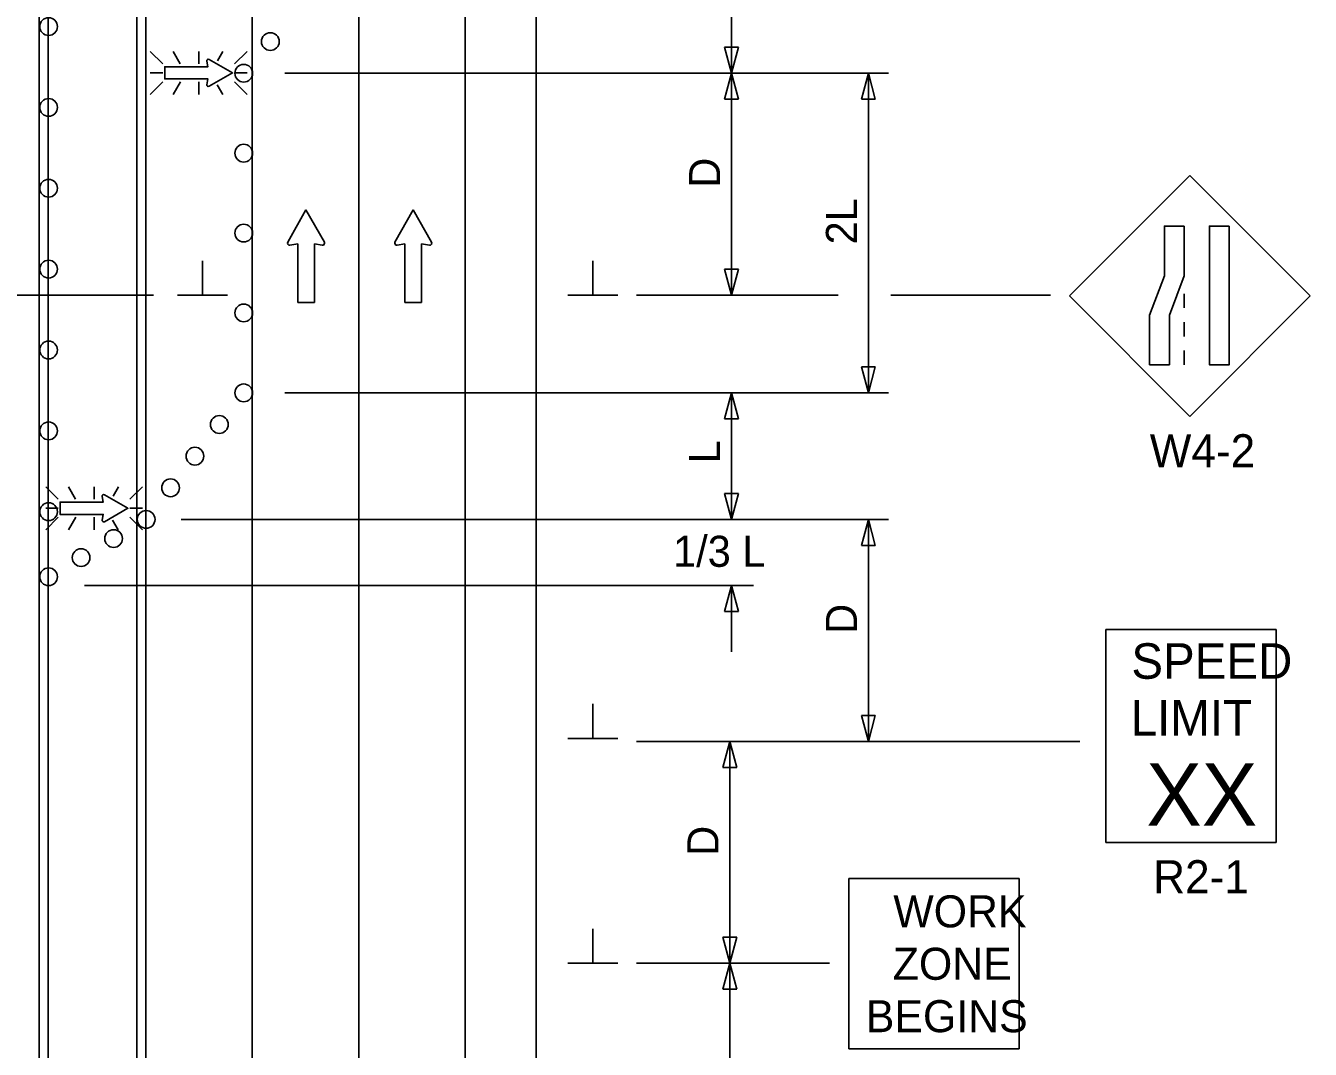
# Model space of a CAD drawing. Extents: x 16732 to 18475, y 5726 to 6929.
# Drawn here: x 17046.3 to 17335.8, y 6299.5 to 6530.1 of the extents above; entities that cross this region are included whole.
import ezdxf

# ---------------------------------------------------------------- set-up
doc = ezdxf.new("R2010")
doc.units = 0
for name, color, linetype in [('ALI_LEGAL_EX', 7, 'Continuous'), ('MT_SCRATCH_LEVEL_E', 7, 'Continuous'), ('PAVT_EDGE_EX', 7, 'Continuous'), ('TRAFFIC_SIGNS_PR', 7, 'Continuous'), ('TYPICAL_TEXT_DIMEN_PR', 7, 'Continuous')]:
    doc.layers.add(name, color=color, linetype=linetype)

msp = doc.modelspace()

# ---------------------------------------------------------------- linework, layer by layer
at = {"layer": 'ALI_LEGAL_EX'}
for p, q in [((17051.36, 6131.68), (17051.36, 6928.96)), ((17071.36, 6131.68), (17071.36, 6928.96)), ((17097.36, 6131.68), (17097.36, 6928.96)), ((17121.36, 6131.68), (17121.36, 6928.96))]:
    msp.add_line(p, q, dxfattribs=at)
for points in [[(17051.36, 6431.68), (17051.36, 6456.68)], [(17071.36, 6431.68), (17071.36, 6456.68)], [(17121.36, 6431.68), (17121.36, 6456.68)], [(17051.36, 6331.68), (17051.36, 6356.68)], [(17071.36, 6331.68), (17071.36, 6356.68)], [(17097.36, 6331.68), (17097.36, 6356.68)], [(17121.36, 6331.68), (17121.36, 6356.68)]]:
    msp.add_lwpolyline(points, dxfattribs=at)
at = {"layer": 'MT_SCRATCH_LEVEL_E'}
for p, q in [((17109.46, 6488.6), (17105.35, 6481.36)), ((17109.46, 6488.6), (17105.35, 6481.36)), ((17113.61, 6481.36), (17109.46, 6488.6)), ((17113.61, 6481.36), (17109.46, 6488.6)), ((17133.63, 6488.6), (17129.52, 6481.36)), ((17133.63, 6488.6), (17129.52, 6481.36)), ((17137.78, 6481.36), (17133.63, 6488.6)), ((17137.78, 6481.36), (17133.63, 6488.6)), ((17105.83, 6480.67), (17107.61, 6480.99)), ((17105.83, 6480.67), (17107.61, 6480.99)), ((17107.61, 6480.99), (17107.61, 6467.73)), ((17107.61, 6480.99), (17107.61, 6467.73)), ((17111.35, 6467.73), (17111.35, 6480.99)), ((17111.35, 6480.99), (17113.13, 6480.67)), ((17111.35, 6467.73), (17111.35, 6480.99)), ((17111.35, 6480.99), (17113.13, 6480.67)), ((17130, 6480.67), (17131.78, 6480.99)), ((17130, 6480.67), (17131.78, 6480.99)), ((17131.78, 6480.99), (17131.78, 6467.73)), ((17131.78, 6480.99), (17131.78, 6467.73)), ((17135.52, 6467.73), (17135.52, 6480.99)), ((17135.52, 6480.99), (17137.3, 6480.67)), ((17135.52, 6467.73), (17135.52, 6480.99)), ((17135.52, 6480.99), (17137.3, 6480.67)), ((17107.61, 6467.73), (17111.35, 6467.73)), ((17107.61, 6467.73), (17111.35, 6467.73)), ((17131.78, 6467.73), (17135.52, 6467.73)), ((17131.78, 6467.73), (17135.52, 6467.73))]:
    msp.add_line(p, q, dxfattribs=at)
for centre, start, end in [((17105.76, 6481.13), 150.4248, 279.9638), ((17105.76, 6481.13), 150.4248, 279.9638), ((17113.2, 6481.13), 260.0362, 29.7731), ((17113.2, 6481.13), 260.0362, 29.7731), ((17129.93, 6481.13), 150.4248, 279.9638), ((17129.93, 6481.13), 150.4248, 279.9638), ((17137.37, 6481.13), 260.0362, 29.7731), ((17137.37, 6481.13), 260.0362, 29.7731)]:
    msp.add_arc(centre, 0.463, start, end, dxfattribs=at)
at = {"layer": 'PAVT_EDGE_EX'}
for p, q in [((17049.36, 6924.76), (17049.36, 6059.7)), ((17073.36, 6924.76), (17073.36, 6059.7)), ((17145.36, 6924.76), (17145.36, 6059.7)), ((17161.36, 6924.76), (17161.36, 6059.7))]:
    msp.add_line(p, q, dxfattribs=at)
at = {"layer": 'TRAFFIC_SIGNS_PR'}
for p, q in [((17077.21, 6521.51), (17074.38, 6524.33)), ((17079.5, 6524.32), (17081.13, 6521.51)), ((17085.29, 6521.51), (17085.29, 6524.32)), ((17090.76, 6524.32), (17089.55, 6522.23)), ((17096.19, 6524.32), (17093.38, 6521.51)), ((17077.21, 6519.47), (17074.38, 6519.47)), ((17077.21, 6517.44), (17074.38, 6514.62)), ((17081.15, 6517.44), (17079.53, 6514.62)), ((17085.29, 6517.44), (17085.29, 6514.62)), ((17093.38, 6519.47), (17096.19, 6519.47)), ((17096.19, 6514.62), (17093.38, 6517.44)), ((17089.47, 6516.81), (17090.73, 6514.62)), ((17308.67, 6496.38), (17281.52, 6469.23)), ((17335.82, 6469.23), (17308.67, 6496.38)), ((17281.52, 6469.23), (17308.67, 6442.08)), ((17307.42, 6469.72), (17307.42, 6466.52)), ((17308.67, 6442.08), (17335.82, 6469.23)), ((17307.42, 6463.32), (17307.42, 6460.12)), ((17307.42, 6456.92), (17307.42, 6453.72)), ((17053.62, 6423.42), (17050.8, 6426.24)), ((17055.92, 6426.24), (17057.55, 6423.42)), ((17061.71, 6423.42), (17061.71, 6426.24)), ((17067.18, 6426.24), (17065.97, 6424.15)), ((17072.61, 6426.24), (17069.79, 6423.42)), ((17053.62, 6421.39), (17050.8, 6421.39)), ((17053.62, 6419.36), (17050.8, 6416.54)), ((17057.57, 6419.36), (17055.95, 6416.54)), ((17061.71, 6419.36), (17061.71, 6416.54)), ((17069.79, 6421.39), (17072.61, 6421.39)), ((17072.61, 6416.54), (17069.79, 6419.36)), ((17065.89, 6418.72), (17067.15, 6416.54)), ((17289.74, 6394.12), (17328.14, 6394.12)), ((17289.74, 6346.12), (17289.74, 6394.12)), ((17328.14, 6346.12), (17328.14, 6394.12)), ((17289.74, 6346.12), (17328.14, 6346.12)), ((17231.84, 6299.62), (17231.84, 6338.02)), ((17231.84, 6338.02), (17270.24, 6338.02)), ((17270.24, 6299.62), (17270.24, 6338.02)), ((17231.84, 6299.62), (17270.24, 6299.62))]:
    msp.add_line(p, q, dxfattribs=at)
for points in [[(17087.12, 6522.15), (17087.35, 6520.86), (17077.62, 6520.86), (17077.62, 6518.11), (17087.35, 6518.11), (17087.12, 6516.81)], [(17087.62, 6516.46), (17092.93, 6519.47), (17087.62, 6522.51)], [(17063.54, 6424.07), (17063.76, 6422.78), (17054.04, 6422.78), (17054.04, 6420.03), (17063.76, 6420.03), (17063.53, 6418.73)], [(17064.04, 6418.37), (17069.35, 6421.39), (17064.03, 6424.43)]]:
    msp.add_lwpolyline(points, dxfattribs=at)
for points in [[(17307.42, 6484.97), (17307.42, 6473.79), (17304.08, 6464.9), (17304.08, 6453.72), (17299.59, 6453.72), (17299.59, 6464.9), (17302.93, 6473.79), (17302.93, 6484.97)], [(17317.56, 6484.97), (17317.56, 6453.72), (17313.07, 6453.72), (17313.07, 6484.97)]]:
    msp.add_lwpolyline(points, close=True, dxfattribs=at)
for centre in [(17051.46, 6529.91), (17101.43, 6526.54), (17095.43, 6519.4), (17051.46, 6511.7), (17095.43, 6501.4), (17051.46, 6493.49), (17095.43, 6483.4), (17051.46, 6475.27), (17095.43, 6465.4), (17051.46, 6457.06), (17095.43, 6447.4), (17089.93, 6440.27), (17051.46, 6438.84), (17084.44, 6433.14), (17078.94, 6426.01), (17051.46, 6420.63), (17073.44, 6418.89), (17066.11, 6414.58), (17058.78, 6410.28), (17051.46, 6405.97)]:
    msp.add_circle(centre, 2, dxfattribs=at)
for centre, start, end in [((17087.45, 6522.21), 61.4833, 189.9593), ((17087.45, 6516.76), 170.7308, 298.8916), ((17063.87, 6424.13), 61.4833, 189.9593), ((17063.87, 6418.67), 170.7308, 298.8916)]:
    msp.add_arc(centre, 0.341, start, end, dxfattribs=at)
at = {"layer": 'TYPICAL_TEXT_DIMEN_PR'}
for p, q in [((17205.36, 6519.39), (17205.36, 6549.97)), ((17205.36, 6519.39), (17203.79, 6525.25)), ((17203.79, 6525.25), (17205.36, 6525.25)), ((17205.36, 6525.25), (17206.93, 6525.25)), ((17206.93, 6525.25), (17205.36, 6519.39)), ((17240.72, 6519.39), (17104.72, 6519.39)), ((17203.79, 6513.53), (17205.36, 6519.39)), ((17205.36, 6519.39), (17205.36, 6469.39)), ((17205.36, 6519.39), (17206.93, 6513.53)), ((17234.64, 6513.53), (17236.21, 6519.39)), ((17236.21, 6519.39), (17236.21, 6447.4)), ((17236.21, 6519.39), (17237.78, 6513.53)), ((17205.36, 6513.53), (17203.79, 6513.53)), ((17206.93, 6513.53), (17205.36, 6513.53)), ((17236.21, 6513.53), (17234.64, 6513.53)), ((17237.78, 6513.53), (17236.21, 6513.53)), ((17086.15, 6469.39), (17086.15, 6477.18)), ((17174.11, 6469.39), (17174.11, 6477.18)), ((17205.36, 6469.39), (17203.79, 6475.25)), ((17203.79, 6475.25), (17205.36, 6475.25)), ((17205.36, 6475.25), (17206.93, 6475.25)), ((17206.93, 6475.25), (17205.36, 6469.39)), ((17075.07, 6469.39), (16899.36, 6469.39)), ((17091.78, 6469.39), (17080.53, 6469.39)), ((17179.74, 6469.39), (17168.49, 6469.39)), ((17183.99, 6469.39), (17229.44, 6469.39)), ((17241.26, 6469.39), (17277.27, 6469.39)), ((17236.21, 6447.4), (17234.64, 6453.26)), ((17234.64, 6453.26), (17236.21, 6453.26)), ((17236.21, 6453.26), (17237.78, 6453.26)), ((17237.78, 6453.26), (17236.21, 6447.4)), ((17240.72, 6447.4), (17104.72, 6447.4)), ((17203.79, 6441.54), (17205.36, 6447.4)), ((17205.36, 6418.89), (17205.36, 6447.4)), ((17205.36, 6447.4), (17206.93, 6441.54)), ((17205.36, 6441.54), (17203.79, 6441.54)), ((17206.93, 6441.54), (17205.36, 6441.54)), ((17205.36, 6418.89), (17203.79, 6424.75)), ((17203.79, 6424.75), (17205.36, 6424.75)), ((17205.36, 6424.75), (17206.93, 6424.75)), ((17206.93, 6424.75), (17205.36, 6418.89)), ((17240.72, 6418.89), (17081.31, 6418.89)), ((17234.64, 6413.03), (17236.21, 6418.89)), ((17236.21, 6418.89), (17237.78, 6413.03)), ((17236.21, 6418.89), (17236.21, 6368.89)), ((17236.21, 6413.03), (17234.64, 6413.03)), ((17237.78, 6413.03), (17236.21, 6413.03)), ((17210.36, 6403.97), (17059.58, 6403.97)), ((17205.36, 6403.97), (17203.79, 6398.11)), ((17205.36, 6403.97), (17205.36, 6389.05)), ((17206.93, 6398.11), (17205.36, 6403.97)), ((17203.79, 6398.11), (17205.36, 6398.11)), ((17205.36, 6398.11), (17206.93, 6398.11)), ((17174.11, 6369.54), (17174.11, 6377.32)), ((17236.21, 6368.89), (17234.64, 6374.75)), ((17234.64, 6374.75), (17236.21, 6374.75)), ((17236.21, 6374.75), (17237.78, 6374.75)), ((17237.78, 6374.75), (17236.21, 6368.89)), ((17179.74, 6369.54), (17168.49, 6369.54)), ((17183.99, 6368.89), (17283.86, 6368.89)), ((17203.42, 6363.03), (17204.99, 6368.89)), ((17204.99, 6368.89), (17204.99, 6318.89)), ((17204.99, 6368.89), (17206.56, 6363.03)), ((17204.99, 6363.03), (17203.42, 6363.03)), ((17206.56, 6363.03), (17204.99, 6363.03)), ((17174.11, 6318.89), (17174.11, 6326.68)), ((17204.99, 6318.89), (17203.42, 6324.75)), ((17203.42, 6324.75), (17204.99, 6324.75)), ((17204.99, 6324.75), (17206.56, 6324.75)), ((17206.56, 6324.75), (17204.99, 6318.89)), ((17179.74, 6318.89), (17168.49, 6318.89)), ((17183.99, 6318.89), (17227.47, 6318.89)), ((17203.42, 6313.03), (17204.99, 6318.89)), ((17204.99, 6318.89), (17204.99, 6268.89)), ((17204.99, 6318.89), (17206.56, 6313.03)), ((17204.99, 6313.03), (17203.42, 6313.03)), ((17206.56, 6313.03), (17204.99, 6313.03))]:
    msp.add_line(p, q, dxfattribs=at)

# ---------------------------------------------------------------- texts
at = {"layer": 'TRAFFIC_SIGNS_PR'}
for s, height, p in [('W4-2', 7.44, (17299.63, 6430.64)), ('SPEED', 8, (17295.5, 6382.99)), ('LIMIT', 8, (17295.34, 6370.19)), ('XX', 14.031, (17298.85, 6349.88)), ('R2-1', 7.44, (17300.41, 6334.68)), ('WORK', 7.217, (17241.84, 6326.99)), ('ZONE', 7.217, (17241.72, 6315.18)), ('BEGINS', 7.217, (17235.65, 6303.37))]:
    msp.add_text(s, height=height, dxfattribs=at).set_placement(p)
at = {"layer": 'TYPICAL_TEXT_DIMEN_PR'}
for s, p in [('D', (17202.8, 6493.61)), ('2L', (17233.65, 6480.84)), ('L', (17202.8, 6431.54)), ('D', (17233.65, 6393.11)), ('D', (17202.43, 6343.11))]:
    msp.add_text(s, height=7, rotation=90, dxfattribs=at).set_placement(p)
msp.add_text('1/3 L', height=7, dxfattribs=at).set_placement((17192.2, 6408.21))

doc.saveas('drawing.dxf')
